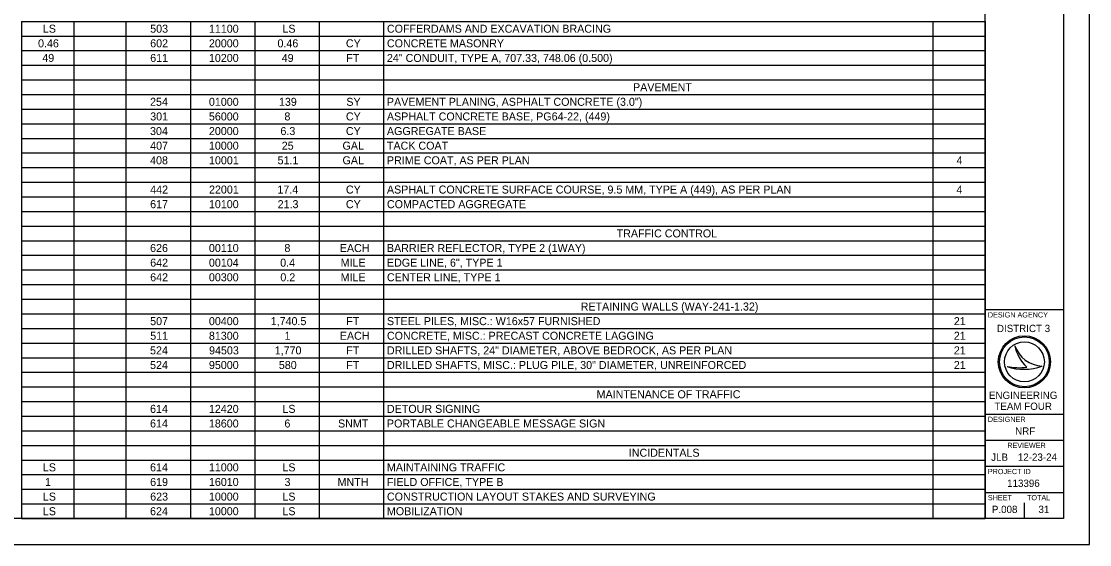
# Model space of a CAD drawing. Extents: x 0 to 34, y 0 to 22.
# Drawn here: x 13.53 to 34, y 0 to 10.02 of the extents above; entities that cross this region are included whole.
import ezdxf

# ---------------------------------------------------------------- set-up
doc = ezdxf.new("R2010")
doc.units = 0
for name, color, linetype in [('Default', 7, 'Continuous'), ('SH_Border', 7, 'Continuous'), ('SH_Cut_Line', 7, 'Continuous'), ('SH_Data', 7, 'Continuous')]:
    doc.layers.add(name, color=color, linetype=linetype)

msp = doc.modelspace()

# ---------------------------------------------------------------- linework, layer by layer
at = {"layer": 'Default'}
for p, q in [((13.53, 10.02), (15.535, 10.02)), ((13.53, 10.02), (13.53, 9.74)), ((14.533, 10.02), (14.533, 9.74)), ((15.535, 10.02), (32, 10.02)), ((15.535, 10.02), (15.535, 9.74)), ((16.769, 10.02), (16.769, 9.74)), ((18.003, 10.02), (18.003, 9.74)), ((19.237, 10.02), (19.237, 9.74)), ((20.471, 10.02), (20.471, 9.74)), ((30.997, 10.02), (30.997, 9.74)), ((32, 10.02), (32, 9.74)), ((13.53, 9.74), (15.535, 9.74)), ((13.53, 9.74), (13.53, 8.9)), ((14.533, 9.74), (14.533, 8.9)), ((15.535, 9.74), (32, 9.74)), ((15.535, 9.74), (15.535, 8.9)), ((16.769, 9.74), (16.769, 8.9)), ((18.003, 9.74), (18.003, 8.9)), ((19.237, 9.74), (19.237, 8.9)), ((20.471, 9.74), (20.471, 8.9)), ((30.997, 9.74), (30.997, 8.9)), ((32, 9.74), (32, 8.9)), ((13.53, 9.46), (15.535, 9.46)), ((15.535, 9.46), (32, 9.46)), ((13.53, 9.18), (15.535, 9.18)), ((15.535, 9.18), (32, 9.18)), ((13.53, 8.9), (15.535, 8.9)), ((13.53, 8.9), (13.53, 8.34)), ((14.533, 8.9), (14.533, 8.34)), ((15.535, 8.9), (32, 8.9)), ((15.535, 8.9), (15.535, 8.34)), ((16.769, 8.9), (16.769, 8.34)), ((18.003, 8.9), (18.003, 8.34)), ((19.237, 8.9), (19.237, 8.34)), ((20.471, 8.9), (20.471, 8.34)), ((30.997, 8.9), (30.997, 8.34)), ((32, 8.9), (32, 8.34)), ((13.53, 8.62), (15.535, 8.62)), ((15.535, 8.62), (32, 8.62)), ((13.53, 8.34), (15.535, 8.34)), ((13.53, 8.34), (13.53, 7.5)), ((14.533, 8.34), (14.533, 7.5)), ((15.535, 8.34), (32, 8.34)), ((15.535, 8.34), (15.535, 7.5)), ((16.769, 8.34), (16.769, 7.5)), ((18.003, 8.34), (18.003, 7.5)), ((19.237, 8.34), (19.237, 7.5)), ((20.471, 8.34), (20.471, 7.5)), ((30.997, 8.34), (30.997, 7.5)), ((32, 8.34), (32, 7.5)), ((13.53, 8.06), (15.535, 8.06)), ((15.535, 8.06), (32, 8.06)), ((13.53, 7.78), (15.535, 7.78)), ((15.535, 7.78), (32, 7.78)), ((13.53, 7.5), (15.535, 7.5)), ((13.53, 7.5), (13.53, 6.94)), ((14.533, 7.5), (14.533, 6.94)), ((15.535, 7.5), (32, 7.5)), ((15.535, 7.5), (15.535, 6.94)), ((16.769, 7.5), (16.769, 6.94)), ((18.003, 7.5), (18.003, 6.94)), ((19.237, 7.5), (19.237, 6.94)), ((20.471, 7.5), (20.471, 6.94)), ((30.997, 7.5), (30.997, 6.94)), ((32, 7.5), (32, 6.94)), ((13.53, 7.22), (15.535, 7.22)), ((15.535, 7.22), (32, 7.22)), ((13.53, 6.94), (15.535, 6.94)), ((13.53, 6.94), (13.53, 6.1)), ((14.533, 6.94), (14.533, 6.1)), ((15.535, 6.94), (32, 6.94)), ((15.535, 6.94), (15.535, 6.1)), ((16.769, 6.94), (16.769, 6.1)), ((18.003, 6.94), (18.003, 6.1)), ((19.237, 6.94), (19.237, 6.1)), ((20.471, 6.94), (20.471, 6.1)), ((30.997, 6.94), (30.997, 6.1)), ((32, 6.94), (32, 6.1)), ((13.53, 6.66), (15.535, 6.66)), ((15.535, 6.66), (32, 6.66)), ((13.53, 6.38), (15.535, 6.38)), ((15.535, 6.38), (32, 6.38)), ((13.53, 6.1), (15.535, 6.1)), ((13.53, 6.1), (13.53, 4.98)), ((14.533, 6.1), (14.533, 4.98)), ((15.535, 6.1), (32, 6.1)), ((15.535, 6.1), (15.535, 4.98)), ((16.769, 6.1), (16.769, 4.98)), ((18.003, 6.1), (18.003, 4.98)), ((19.237, 6.1), (19.237, 4.98)), ((20.471, 6.1), (20.471, 4.98)), ((30.997, 6.1), (30.997, 4.98)), ((32, 6.1), (32, 4.98)), ((13.53, 5.82), (15.535, 5.82)), ((15.535, 5.82), (32, 5.82)), ((13.53, 5.54), (15.535, 5.54)), ((15.535, 5.54), (32, 5.54)), ((13.53, 5.26), (15.535, 5.26)), ((15.535, 5.26), (32, 5.26)), ((13.53, 4.98), (15.535, 4.98)), ((13.53, 4.98), (13.53, 4.7)), ((14.533, 4.98), (14.533, 4.7)), ((15.535, 4.98), (32, 4.98)), ((15.535, 4.98), (15.535, 4.7)), ((16.769, 4.98), (16.769, 4.7)), ((18.003, 4.98), (18.003, 4.7)), ((19.237, 4.98), (19.237, 4.7)), ((20.471, 4.98), (20.471, 4.7)), ((30.997, 4.98), (30.997, 4.7)), ((32, 4.98), (32, 4.7)), ((13.53, 4.7), (15.535, 4.7)), ((13.53, 4.7), (13.53, 3.58)), ((14.533, 4.7), (14.533, 3.58)), ((15.535, 4.7), (32, 4.7)), ((15.535, 4.7), (15.535, 3.58)), ((16.769, 4.7), (16.769, 3.58)), ((18.003, 4.7), (18.003, 3.58)), ((19.237, 4.7), (19.237, 3.58)), ((20.471, 4.7), (20.471, 3.58)), ((30.997, 4.7), (30.997, 3.58)), ((32, 4.7), (32, 3.58)), ((13.53, 4.42), (15.535, 4.42)), ((15.535, 4.42), (32, 4.42)), ((13.53, 4.14), (15.535, 4.14)), ((15.535, 4.14), (32, 4.14)), ((13.53, 3.86), (15.535, 3.86)), ((15.535, 3.86), (32, 3.86)), ((13.53, 3.58), (15.535, 3.58)), ((13.53, 3.58), (13.53, 3.3)), ((14.533, 3.58), (14.533, 3.3)), ((15.535, 3.58), (32, 3.58)), ((15.535, 3.58), (15.535, 3.3)), ((16.769, 3.58), (16.769, 3.3)), ((18.003, 3.58), (18.003, 3.3)), ((19.237, 3.58), (19.237, 3.3)), ((20.471, 3.58), (20.471, 3.3)), ((30.997, 3.58), (30.997, 3.3)), ((32, 3.58), (32, 3.3)), ((13.53, 3.3), (15.535, 3.3)), ((13.53, 3.3), (13.53, 2.18)), ((14.533, 3.3), (14.533, 2.18)), ((15.535, 3.3), (32, 3.3)), ((15.535, 3.3), (15.535, 2.18)), ((16.769, 3.3), (16.769, 2.18)), ((18.003, 3.3), (18.003, 2.18)), ((19.237, 3.3), (19.237, 2.18)), ((20.471, 3.3), (20.471, 2.18)), ((30.997, 3.3), (30.997, 2.18)), ((32, 3.3), (32, 2.18)), ((13.53, 3.02), (15.535, 3.02)), ((15.535, 3.02), (32, 3.02)), ((13.53, 2.74), (15.535, 2.74)), ((15.535, 2.74), (32, 2.74)), ((13.53, 2.46), (15.535, 2.46)), ((15.535, 2.46), (32, 2.46)), ((13.53, 2.18), (15.535, 2.18)), ((13.53, 2.18), (13.53, 1.9)), ((14.533, 2.18), (14.533, 1.9)), ((15.535, 2.18), (32, 2.18)), ((15.535, 2.18), (15.535, 1.9)), ((16.769, 2.18), (16.769, 1.9)), ((18.003, 2.18), (18.003, 1.9)), ((19.237, 2.18), (19.237, 1.9)), ((20.471, 2.18), (20.471, 1.9)), ((30.997, 2.18), (30.997, 1.9)), ((32, 2.18), (32, 1.9)), ((13.53, 1.9), (15.535, 1.9)), ((13.53, 1.9), (13.53, 0.78)), ((14.533, 1.9), (14.533, 0.78)), ((15.535, 1.9), (32, 1.9)), ((15.535, 1.9), (15.535, 0.78)), ((16.769, 1.9), (16.769, 0.78)), ((18.003, 1.9), (18.003, 0.78)), ((19.237, 1.9), (19.237, 0.78)), ((20.471, 1.9), (20.471, 0.78)), ((30.997, 1.9), (30.997, 0.78)), ((32, 1.9), (32, 0.78)), ((13.53, 1.62), (15.535, 1.62)), ((15.535, 1.62), (32, 1.62)), ((13.53, 1.34), (15.535, 1.34)), ((15.535, 1.34), (32, 1.34)), ((13.53, 1.06), (15.535, 1.06)), ((15.535, 1.06), (32, 1.06)), ((13.53, 0.78), (15.535, 0.78)), ((13.53, 0.78), (13.53, 0.5)), ((14.533, 0.78), (14.533, 0.5)), ((15.535, 0.78), (32, 0.78)), ((15.535, 0.78), (15.535, 0.5)), ((16.769, 0.78), (16.769, 0.5)), ((18.003, 0.78), (18.003, 0.5)), ((19.237, 0.78), (19.237, 0.5)), ((20.471, 0.78), (20.471, 0.5)), ((30.997, 0.78), (30.997, 0.5)), ((32, 0.78), (32, 0.5)), ((13.53, 0.5), (15.535, 0.5)), ((15.535, 0.5), (32, 0.5))]:
    msp.add_line(p, q, dxfattribs=at)
at = {"layer": 'SH_Border'}
for p, q in [((32, 0.5), (32, 21.5)), ((32, 4.5), (33.5, 4.5)), ((32, 2.5), (33.5, 2.5)), ((32, 2), (33.5, 2)), ((32, 1.5), (33.5, 1.5)), ((32, 1), (33.5, 1))]:
    msp.add_line(p, q, dxfattribs=at)
msp.add_lwpolyline([(1.5, 21.5), (33.5, 21.5), (33.5, 0.5), (1.5, 0.5)], close=True, dxfattribs=at)
at = {"layer": 'SH_Cut_Line'}
msp.add_lwpolyline([(0, 0), (34, 0), (34, 22), (0, 22)], close=True, dxfattribs=at)
at = {"layer": 'SH_Data'}
for p, q in [((32.567, 3.81), (32.567, 3.81)), ((32.75, 3.5), (32.75, 3.5)), ((32.417, 3.41), (32.417, 3.41)), ((33.087, 3.419), (33.087, 3.419)), ((32.375, 0.675), (32.375, 0.675)), ((32.75, 0.5), (32.75, 0.8))]:
    msp.add_line(p, q, dxfattribs=at)
for radius in [0.5, 0.477, 0.477, 0.382]:
    msp.add_circle((32.75, 3.5), radius, dxfattribs=at)
for centre, radius, start, end in [((33.116, 3.998), 0.58, 198.9257, 198.9319), ((33.347, 3.97), 0.796, 191.6379, 191.6421), ((33.116, 3.998), 0.58, 198.9319, 267.1657), ((33.347, 3.97), 0.796, 191.6421, 226.0947), ((32.739, 4.37), 1.013, 251.4576, 290.0832), ((32.648, 4.654), 1.266, 259.4964, 259.4995), ((32.739, 4.37), 1.013, 251.4527, 251.4576), ((32.648, 4.654), 1.266, 259.4995, 276.6672)]:
    msp.add_arc(centre, radius, start, end, dxfattribs=at)

# ---------------------------------------------------------------- texts
at = {"layer": 'Default'}
for s, height, p in [('LS', 0.1533, (13.943, 9.803)), ('503', 0.1533, (15.999, 9.803)), ('11100', 0.1533, (17.124, 9.803)), ('LS', 0.1533, (18.532, 9.803)), ('COFFERDAMS AND EXCAVATION BRACING', 0.15333, (20.535, 9.803)), ('0.46', 0.1533, (13.85, 9.523)), ('602', 0.1533, (15.999, 9.523)), ('20000', 0.1533, (17.124, 9.523)), ('0.46', 0.1533, (18.438, 9.523)), ('CY', 0.1533, (19.749, 9.523)), ('CONCRETE MASONRY', 0.15333, (20.535, 9.523)), ('49', 0.1533, (13.931, 9.243)), ('611', 0.1533, (15.999, 9.243)), ('10200', 0.1533, (17.124, 9.243)), ('49', 0.1533, (18.519, 9.243)), ('FT', 0.1533, (19.756, 9.243)), ('24" CONDUIT, TYPE A, 707.33, 748.06 (0.500)', 0.15333, (20.535, 9.243)), ('PAVEMENT', 0.1533, (25.251, 8.683)), ('254', 0.1533, (15.996, 8.403)), ('01000', 0.1533, (17.124, 8.403)), ('139', 0.1533, (18.466, 8.403)), ('SY', 0.1533, (19.757, 8.403)), ('PAVEMENT PLANING, ASPHALT CONCRETE (3.0")', 0.15333, (20.535, 8.403)), ('301', 0.1533, (15.999, 8.123)), ('56000', 0.1533, (17.124, 8.123)), ('8', 0.153, (18.571, 8.123)), ('CY', 0.1533, (19.749, 8.123)), ('ASPHALT CONCRETE BASE, PG64-22, (449)', 0.15333, (20.535, 8.123)), ('304', 0.1533, (15.996, 7.843)), ('20000', 0.1533, (17.124, 7.843)), ('6.3', 0.1533, (18.494, 7.843)), ('CY', 0.1533, (19.749, 7.843)), ('AGGREGATE BASE', 0.15333, (20.535, 7.843)), ('407', 0.1533, (15.998, 7.563)), ('10000', 0.1533, (17.124, 7.563)), ('25', 0.1533, (18.52, 7.563)), ('GAL', 0.1533, (19.684, 7.563)), ('TACK COAT', 0.1533, (20.535, 7.563)), ('408', 0.1533, (15.997, 7.283)), ('10001', 0.1533, (17.126, 7.283)), ('51.1', 0.1533, (18.44, 7.283)), ('GAL', 0.1533, (19.684, 7.283)), ('PRIME COAT, AS PER PLAN', 0.15333, (20.535, 7.283)), ('4', 0.153, (31.449, 7.283)), ('442', 0.1533, (15.999, 6.723)), ('22001', 0.1533, (17.126, 6.723)), ('17.4', 0.1533, (18.437, 6.723)), ('CY', 0.1533, (19.749, 6.723)), ('ASPHALT CONCRETE SURFACE COURSE, 9.5 MM, TYPE A (449), AS PER PLAN', 0.15333, (20.535, 6.723)), ('4', 0.153, (31.449, 6.723)), ('617', 0.1533, (15.998, 6.443)), ('10100', 0.1533, (17.124, 6.443)), ('21.3', 0.1533, (18.441, 6.443)), ('CY', 0.1533, (19.749, 6.443)), ('COMPACTED AGGREGATE', 0.15333, (20.535, 6.443)), ('TRAFFIC CONTROL', 0.15333, (24.937, 5.883)), ('626', 0.1533, (15.997, 5.603)), ('00110', 0.1533, (17.124, 5.603)), ('8', 0.153, (18.571, 5.603)), ('EACH', 0.1533, (19.632, 5.603)), ('BARRIER REFLECTOR, TYPE 2 (1WAY)', 0.15333, (20.535, 5.603)), ('642', 0.1533, (15.999, 5.323)), ('00104', 0.1533, (17.124, 5.323)), ('0.4', 0.1533, (18.49, 5.323)), ('MILE', 0.1533, (19.648, 5.323)), ('EDGE LINE, 6", TYPE 1', 0.15333, (20.535, 5.323)), ('642', 0.1533, (15.999, 5.043)), ('00300', 0.1533, (17.124, 5.043)), ('0.2', 0.1533, (18.493, 5.043)), ('MILE', 0.1533, (19.648, 5.043)), ('CENTER LINE, TYPE 1', 0.15333, (20.535, 5.043)), ('RETAINING WALLS (WAY-241-1.32)', 0.15333, (24.247, 4.483)), ('507', 0.1533, (15.998, 4.203)), ('00400', 0.1533, (17.124, 4.203)), ('1,740.5', 0.1533, (18.308, 4.203)), ('FT', 0.1533, (19.756, 4.203)), ('STEEL PILES, MISC.: W16x57 FURNISHED', 0.15333, (20.535, 4.203)), ('21', 0.1533, (31.398, 4.203)), ('511', 0.1533, (15.999, 3.923)), ('81300', 0.1533, (17.124, 3.923)), ('1', 0.153, (18.573, 3.923)), ('EACH', 0.1533, (19.632, 3.923)), ('CONCRETE, MISC.: PRECAST CONCRETE LAGGING', 0.15333, (20.535, 3.923)), ('21', 0.1533, (31.398, 3.923)), ('524', 0.1533, (15.996, 3.643)), ('94503', 0.1533, (17.127, 3.643)), ('1,770', 0.1533, (18.385, 3.643)), ('FT', 0.1533, (19.756, 3.643)), ('DRILLED SHAFTS, 24" DIAMETER, ABOVE BEDROCK, AS PER PLAN', 0.15333, (20.535, 3.643)), ('21', 0.1533, (31.398, 3.643)), ('524', 0.1533, (15.996, 3.363)), ('95000', 0.1533, (17.124, 3.363)), ('580', 0.1533, (18.464, 3.363)), ('FT', 0.1533, (19.756, 3.363)), ('DRILLED SHAFTS, MISC.: PLUG PILE, 30" DIAMETER, UNREINFORCED', 0.15333, (20.535, 3.363)), ('21', 0.1533, (31.398, 3.363)), ('MAINTENANCE OF TRAFFIC', 0.15333, (24.553, 2.803)), ('614', 0.1533, (15.996, 2.523)), ('12420', 0.1533, (17.124, 2.523)), ('LS', 0.1533, (18.532, 2.523)), ('DETOUR SIGNING', 0.15333, (20.535, 2.523)), ('614', 0.1533, (15.996, 2.243)), ('18600', 0.1533, (17.124, 2.243)), ('6', 0.153, (18.571, 2.243)), ('SNMT', 0.1533, (19.598, 2.243)), ('PORTABLE CHANGEABLE MESSAGE SIGN', 0.15333, (20.535, 2.243)), ('INCIDENTALS', 0.15333, (25.17, 1.683)), ('LS', 0.1533, (13.943, 1.403)), ('614', 0.1533, (15.996, 1.403)), ('11000', 0.1533, (17.124, 1.403)), ('LS', 0.1533, (18.532, 1.403)), ('MAINTAINING TRAFFIC', 0.15333, (20.535, 1.403)), ('1', 0.153, (13.984, 1.123)), ('619', 0.1533, (15.998, 1.123)), ('16010', 0.1533, (17.124, 1.123)), ('3', 0.153, (18.573, 1.123)), ('MNTH', 0.1533, (19.589, 1.123)), ('FIELD OFFICE, TYPE B', 0.15333, (20.535, 1.123)), ('LS', 0.1533, (13.943, 0.843)), ('623', 0.1533, (15.999, 0.843)), ('10000', 0.1533, (17.124, 0.843)), ('LS', 0.1533, (18.532, 0.843)), ('CONSTRUCTION LAYOUT STAKES AND SURVEYING', 0.15333, (20.535, 0.843)), ('LS', 0.1533, (13.943, 0.563)), ('624', 0.1533, (15.996, 0.563)), ('10000', 0.1533, (17.124, 0.563)), ('LS', 0.1533, (18.532, 0.563)), ('MOBILIZATION', 0.15333, (20.535, 0.563))]:
    msp.add_text(s, height=height, dxfattribs=at).set_placement(p)
at = {"layer": 'SH_Data'}
for s, height, p in [('DESIGN AGENCY', 0.1, (32.05, 4.35)), ('DISTRICT 3', 0.14, (32.224, 4.07)), ('ENGINEERING', 0.14, (32.071, 2.79)), ('TEAM FOUR', 0.14, (32.175, 2.58)), ('DESIGNER', 0.1, (32.05, 2.35)), ('NRF', 0.14, (32.573, 2.105)), ('REVIEWER', 0.1, (32.422, 1.85)), ('JLB', 0.14, (32.113, 1.605)), ('12-23-24', 0.14, (32.625, 1.605)), ('PROJECT ID', 0.1, (32.05, 1.35)), ('113396', 0.14, (32.419, 1.105)), ('SHEET', 0.1, (32.05, 0.85)), ('TOTAL', 0.1, (32.8, 0.85)), ('P.008', 0.14, (32.127, 0.605)), ('31', 0.14, (33.019, 0.605))]:
    msp.add_text(s, height=height, dxfattribs=at).set_placement(p)

doc.saveas('drawing.dxf')
